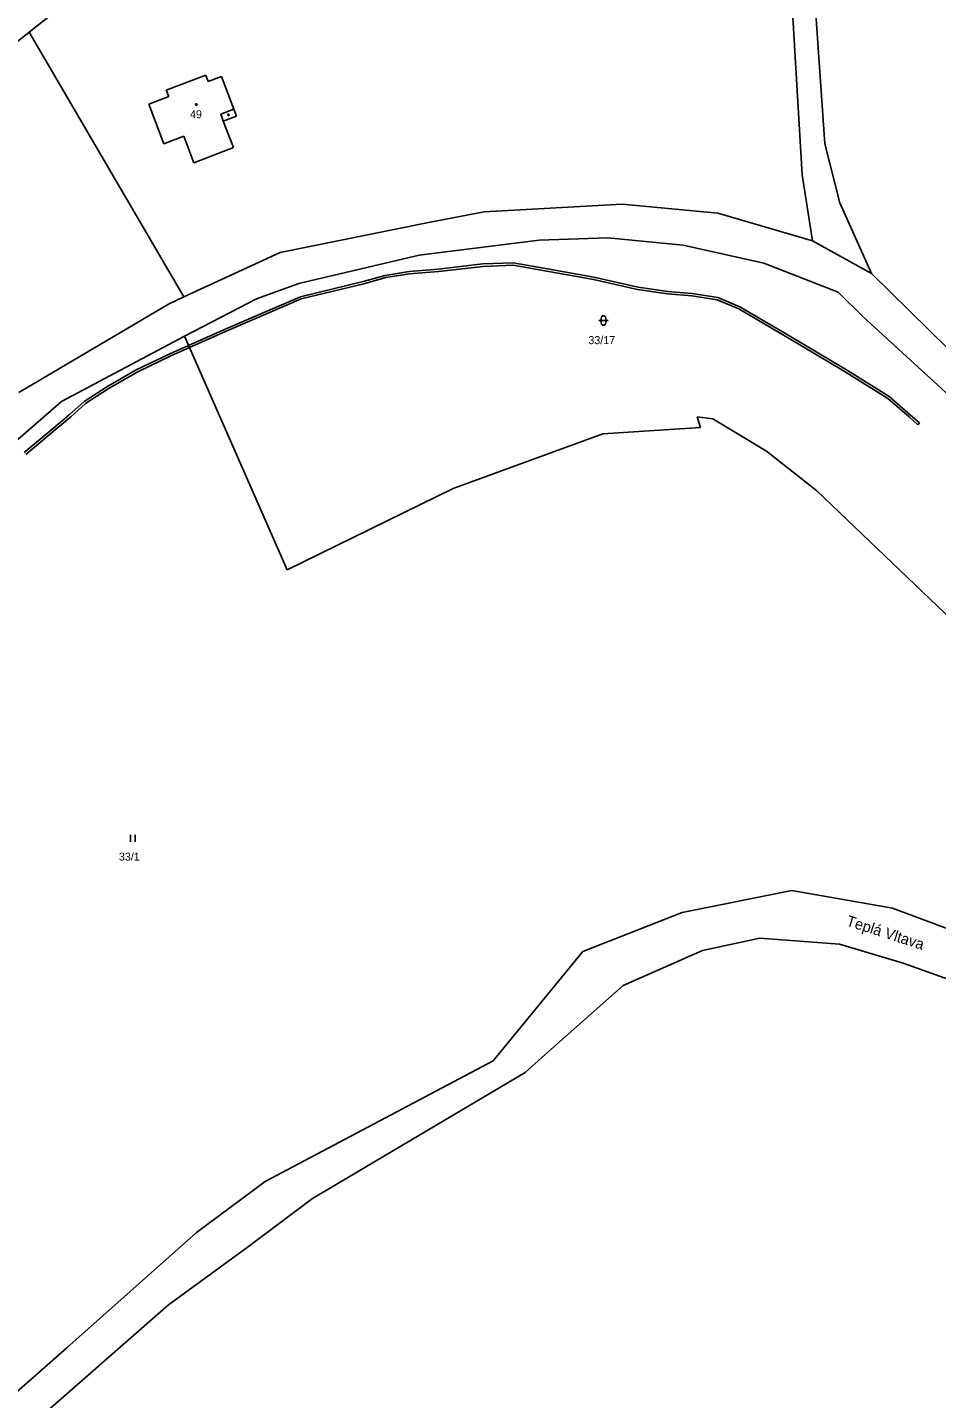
# Model space of a CAD drawing. Extents: x -811039 to -805820, y -1161436 to -1155864.
# Drawn here: x -810361.7 to -810168.6, y -1161047.6 to -1160756.4 of the extents above; entities that cross this region are included whole.
import ezdxf

# ---------------------------------------------------------------- set-up
doc = ezdxf.new("R2010")
doc.units = 0
for name, color, linetype in [('Default', 7, 'Continuous'), ('Hranice kat_území', 7, 'Continuous'), ('Hranice parcel', 7, 'Continuous'), ('Parcelní čísla', 7, 'Continuous'), ('Pop  PČ popisy', 7, 'Continuous'), ('Vnitřní kresba', 7, 'Continuous'), ('Věcná břemena k části', 7, 'Continuous'), ('Značky budov', 7, 'Continuous'), ('Značky kultur', 7, 'Continuous')]:
    doc.layers.add(name, color=color, linetype=linetype)

# ---------------------------------------------------------------- blocks, each defined once
blk = doc.blocks.new('306')
at = {"layer": 'Default'}
for p, q in [((-0.5, 1.5), (-0.5, 0)), ((0.5, 0), (0.5, 1.5))]:
    blk.add_line(p, q, dxfattribs=at)
blk = doc.blocks.new('316')
at = {"layer": 'Default'}
for points in [[(-1, 1), (0.27, 1), (1, 1)], [(-0.5, 1.5), (-0.4, 1.79), (-0.15, 1.97), (0.16, 1.97), (0.41, 1.79), (0.51, 1.5), (0.51, 0.5), (0.41, 0.21), (0.16, 0.03), (-0.15, 0.03), (-0.4, 0.21), (-0.5, 0.5), (-0.5, 1.5)]]:
    blk.add_lwpolyline(points, dxfattribs=at)
blk = doc.blocks.new('402')
at = {"layer": 'Default'}
blk.add_lwpolyline([(0.09, 0.15), (0.18, 0), (0.09, -0.15), (-0.09, -0.15), (-0.18, 0), (-0.09, 0.15), (0.09, 0.15)], dxfattribs=at)

msp = doc.modelspace()

# ---------------------------------------------------------------- linework, layer by layer
at = {"layer": 'Hranice kat_území'}
for p, q in [((-810206.13, -1160949.81), (-810218.33, -1160952.41)), ((-810189.22, -1160951.08), (-810206.13, -1160949.81)), ((-810175.68, -1160955.12), (-810189.22, -1160951.08)), ((-810218.33, -1160952.41), (-810235.16, -1160959.86)), ((-810136.07, -1160969.26), (-810175.68, -1160955.12)), ((-810235.16, -1160959.86), (-810251.85, -1160974.57)), ((-810251.85, -1160974.57), (-810256, -1160978.34)), ((-810256, -1160978.34), (-810301.19, -1161005.11)), ((-810301.19, -1161005.11), (-810314.75, -1161015.27)), ((-810314.75, -1161015.27), (-810331.78, -1161027.66)), ((-810331.78, -1161027.66), (-810373.79, -1161064.42))]:
    msp.add_line(p, q, dxfattribs=at)
at = {"layer": 'Hranice parcel'}
for p, q in [((-810361.37, -1160757.38), (-810315.18, -1160720.58)), ((-810199.32, -1160750.66), (-810197.13, -1160787.69)), ((-810192.37, -1160781.09), (-810194.28, -1160753.55)), ((-810361.37, -1160757.38), (-810378.26, -1160770.87)), ((-810328.51, -1160813.58), (-810361.37, -1160757.38)), ((-810332.25, -1160769.66), (-810323.84, -1160766.46)), ((-810323.84, -1160766.46), (-810323.31, -1160767.87)), ((-810323.31, -1160767.87), (-810320.5, -1160766.81)), ((-810320.5, -1160766.81), (-810317.88, -1160773.72)), ((-810335.93, -1160772.65), (-810331.72, -1160771.06)), ((-810331.72, -1160771.06), (-810332.25, -1160769.66)), ((-810332.74, -1160781.07), (-810335.93, -1160772.65)), ((-810317.88, -1160773.72), (-810317.32, -1160775.22)), ((-810317.32, -1160775.22), (-810320.12, -1160776.28)), ((-810320.12, -1160776.28), (-810317.99, -1160781.88)), ((-810328.53, -1160779.47), (-810332.74, -1160781.07)), ((-810326.4, -1160785.08), (-810328.53, -1160779.47)), ((-810317.99, -1160781.88), (-810326.4, -1160785.08)), ((-810189.12, -1160793.64), (-810192.37, -1160781.09)), ((-810197.13, -1160787.69), (-810194.97, -1160801.67)), ((-810264.71, -1160795.49), (-810235.41, -1160793.88)), ((-810235.41, -1160793.88), (-810215.08, -1160795.78)), ((-810182.46, -1160808.65), (-810189.12, -1160793.64)), ((-810276.56, -1160797.77), (-810264.71, -1160795.49)), ((-810215.08, -1160795.78), (-810194.97, -1160801.67)), ((-810308.08, -1160804.19), (-810276.56, -1160797.77)), ((-810253.04, -1160801.56), (-810278.52, -1160804.7)), ((-810238.45, -1160801.05), (-810253.04, -1160801.56)), ((-810222.46, -1160802.59), (-810238.45, -1160801.05)), ((-810205.29, -1160806.45), (-810222.46, -1160802.59)), ((-810194.97, -1160801.67), (-810182.46, -1160808.65)), ((-810328.51, -1160813.58), (-810308.08, -1160804.19)), ((-810304.09, -1160810.76), (-810278.52, -1160804.7)), ((-810189.5, -1160812.58), (-810205.29, -1160806.45)), ((-810182.46, -1160808.65), (-810157.76, -1160832.87)), ((-810304.09, -1160810.76), (-810313.05, -1160813.98)), ((-810331.75, -1160815.16), (-810328.51, -1160813.58)), ((-810328.4, -1160821.91), (-810313.05, -1160813.98)), ((-810184.17, -1160817.79), (-810189.5, -1160812.58)), ((-810363.54, -1160833.87), (-810331.75, -1160815.16)), ((-810164.15, -1160836.13), (-810184.17, -1160817.79)), ((-810328.4, -1160821.91), (-810354.5, -1160835.77)), ((-810328.4, -1160821.91), (-810306.55, -1160871.55)), ((-810399.4, -1160874.7), (-810354.5, -1160835.77)), ((-810218.74, -1160841.34), (-810219.44, -1160839.06)), ((-810219.44, -1160839.06), (-810216.11, -1160839.45)), ((-810216.11, -1160839.45), (-810204.7, -1160846.34)), ((-810271.31, -1160854.25), (-810239.5, -1160842.7)), ((-810239.5, -1160842.7), (-810218.74, -1160841.34)), ((-810204.7, -1160846.34), (-810194.01, -1160854.78)), ((-810306.55, -1160871.55), (-810271.31, -1160854.25)), ((-810194.01, -1160854.78), (-810150.43, -1160896.48)), ((-810222.65, -1160944.36), (-810199.37, -1160939.68)), ((-810199.37, -1160939.68), (-810177.95, -1160943.44)), ((-810243.73, -1160952.59), (-810222.65, -1160944.36)), ((-810177.95, -1160943.44), (-810136.98, -1160958.63)), ((-810262.83, -1160975.82), (-810243.73, -1160952.59)), ((-810311.21, -1161001.5), (-810262.83, -1160975.82)), ((-810325.85, -1161012.33), (-810311.21, -1161001.5)), ((-810353.34, -1161036.78), (-810325.85, -1161012.33)), ((-810376.47, -1161057.05), (-810353.34, -1161036.78))]:
    msp.add_line(p, q, dxfattribs=at)
at = {"layer": 'Vnitřní kresba'}
for p, q in [((-810320.68, -1160774.79), (-810317.88, -1160773.72)), ((-810320.12, -1160776.28), (-810320.68, -1160774.79))]:
    msp.add_line(p, q, dxfattribs=at)
at = {"layer": 'Věcná břemena k části'}
for p, q in [((-810290.42, -1160810.35), (-810285.72, -1160809.02)), ((-810285.72, -1160809.02), (-810280.64, -1160808.17)), ((-810280.58, -1160808.67), (-810285.62, -1160809.5)), ((-810280.64, -1160808.17), (-810274.45, -1160807.69)), ((-810274.41, -1160808.19), (-810280.58, -1160808.67)), ((-810274.45, -1160807.69), (-810264.97, -1160806.6)), ((-810264.93, -1160807.1), (-810274.41, -1160808.19)), ((-810264.97, -1160806.6), (-810258.54, -1160806.36)), ((-810258.58, -1160806.86), (-810264.93, -1160807.1)), ((-810251.37, -1160808.11), (-810258.58, -1160806.86)), ((-810258.54, -1160806.36), (-810251.29, -1160807.61)), ((-810241.5, -1160809.87), (-810251.37, -1160808.11)), ((-810251.29, -1160807.61), (-810241.4, -1160809.37)), ((-810303.74, -1160813.55), (-810290.42, -1160810.35)), ((-810290.3, -1160810.83), (-810303.58, -1160814.03)), ((-810285.62, -1160809.5), (-810290.3, -1160810.83)), ((-810232.11, -1160811.99), (-810241.5, -1160809.87)), ((-810241.4, -1160809.37), (-810232.01, -1160811.49)), ((-810225.74, -1160812.91), (-810232.11, -1160811.99)), ((-810232.01, -1160811.49), (-810225.68, -1160812.41)), ((-810313.63, -1160817.81), (-810303.74, -1160813.55)), ((-810303.58, -1160814.03), (-810313.43, -1160818.27)), ((-810220.59, -1160813.34), (-810225.74, -1160812.91)), ((-810225.68, -1160812.41), (-810220.53, -1160812.84)), ((-810215.23, -1160814.19), (-810220.59, -1160813.34)), ((-810220.53, -1160812.84), (-810215.09, -1160813.71)), ((-810210.62, -1160816.15), (-810215.23, -1160814.19)), ((-810215.09, -1160813.71), (-810210.4, -1160815.71)), ((-810321, -1160820.99), (-810313.63, -1160817.81)), ((-810199.92, -1160822.43), (-810210.62, -1160816.15)), ((-810210.4, -1160815.71), (-810199.66, -1160821.99)), ((-810313.43, -1160818.27), (-810320.8, -1160821.45)), ((-810327.52, -1160823.9), (-810321, -1160820.99)), ((-810320.8, -1160821.45), (-810327.32, -1160824.36)), ((-810188.37, -1160829.29), (-810199.92, -1160822.43)), ((-810199.66, -1160821.99), (-810188.11, -1160828.87)), ((-810338.63, -1160829.11), (-810331.46, -1160825.65)), ((-810331.24, -1160826.11), (-810338.39, -1160829.55)), ((-810331.46, -1160825.65), (-810327.52, -1160823.9)), ((-810327.32, -1160824.36), (-810331.24, -1160826.11)), ((-810344.86, -1160832.67), (-810338.63, -1160829.11)), ((-810338.39, -1160829.55), (-810344.6, -1160833.09)), ((-810178.94, -1160835.17), (-810188.37, -1160829.29)), ((-810188.11, -1160828.87), (-810178.64, -1160834.77)), ((-810349.7, -1160835.81), (-810344.86, -1160832.67)), ((-810344.6, -1160833.09), (-810349.4, -1160836.21)), ((-810174.43, -1160839.07), (-810178.94, -1160835.17)), ((-810178.64, -1160834.77), (-810174.11, -1160838.69)), ((-810352.87, -1160838.65), (-810349.7, -1160835.81)), ((-810349.4, -1160836.21), (-810352.55, -1160839.03)), ((-810356.12, -1160841.37), (-810352.87, -1160838.65)), ((-810352.55, -1160839.03), (-810355.8, -1160841.75)), ((-810172.55, -1160840.73), (-810174.43, -1160839.07)), ((-810174.11, -1160838.69), (-810172.22, -1160840.36)), ((-810172.22, -1160840.36), (-810172.55, -1160840.73)), ((-810362.41, -1160846.66), (-810356.12, -1160841.37)), ((-810355.8, -1160841.75), (-810362.11, -1160847.06))]:
    msp.add_line(p, q, dxfattribs=at)

# ---------------------------------------------------------------- block references
at = {"layer": 'Značky budov'}
for p in [(-810325.87, -1160772.74), (-810319.02, -1160774.91)]:
    msp.add_blockref('402', p, dxfattribs=at)
at = {"layer": 'Značky kultur'}
for name, p in [('316', (-810239.36, -1160819.6)), ('306', (-810339.36, -1160929.33))]:
    msp.add_blockref(name, p, dxfattribs=at)

# ---------------------------------------------------------------- texts
at = {"layer": 'Parcelní čísla'}
for s, p in [('49', (-810327.2, -1160775.65)), ('33/17', (-810242.57, -1160823.62)), ('33/1', (-810342.3, -1160933.32))]:
    msp.add_text(s, height=1.7, dxfattribs=at).set_placement(p)
at = {"layer": 'Pop  PČ popisy'}
msp.add_text('Teplá Vltava', height=2.3, rotation=342.228, dxfattribs=at).set_placement((-810187.96, -1160947.07))

doc.saveas('drawing.dxf')
